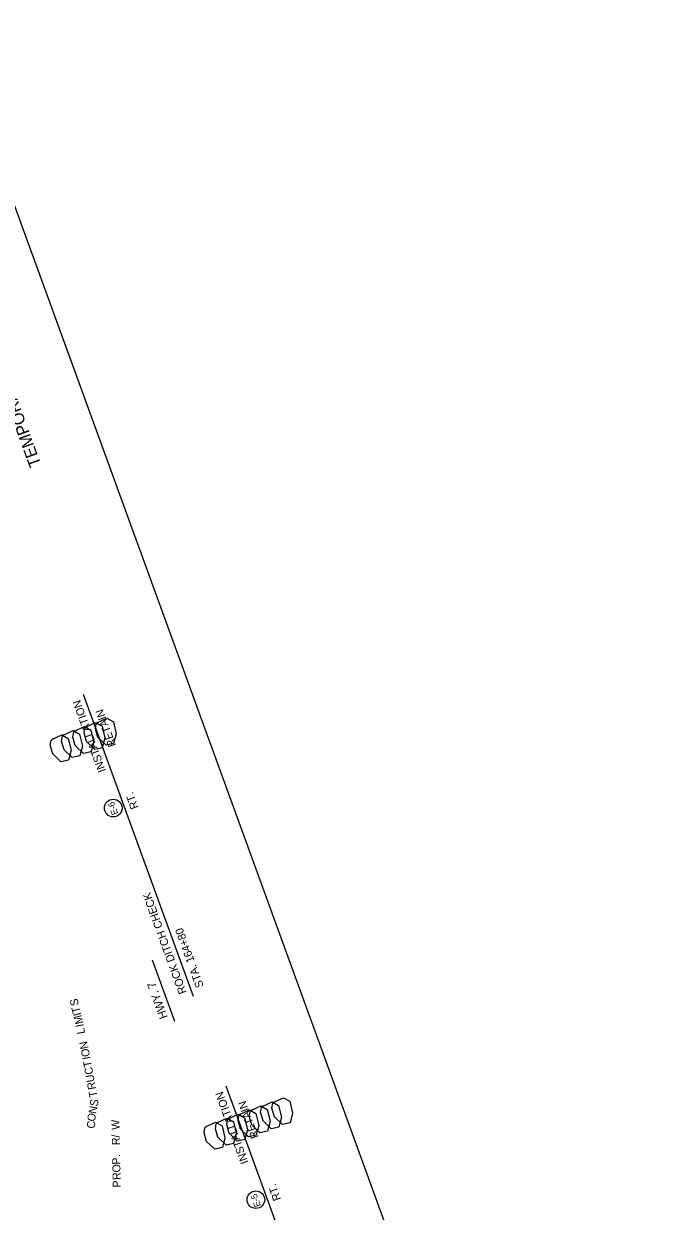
# Model space of a CAD drawing. Extents: x 986289 to 987754, y 1871116 to 1872971.
# Drawn here: x 987265 to 987754, y 1872081 to 1872971 of the extents above; entities that cross this region are included whole.
import ezdxf

# ---------------------------------------------------------------- set-up
doc = ezdxf.new("R2010")
doc.units = 0
for name, color, linetype in [('1', 7, 'Continuous'), ('44', 7, 'Continuous'), ('60', 7, 'Continuous'), ('NO PLOT', 7, 'Continuous'), ('R_Draft', 7, 'Continuous'), ('S_TREE', 7, 'Continuous')]:
    doc.layers.add(name, color=color, linetype=linetype)

msp = doc.modelspace()

# ---------------------------------------------------------------- linework, layer by layer
at = {"layer": '1'}
for centre in [(987331.7, 1872383.22), (987438.58, 1872089.57)]:
    msp.add_circle(centre, 6.61, dxfattribs=at)
at = {"layer": '44'}
for p, q in [((987391.94, 1872241.79), (987309.51, 1872468.26)), ((987377.86, 1872223.17), (987361.16, 1872269.07)), ((987498.82, 1871948.14), (987416.39, 1872174.61))]:
    msp.add_line(p, q, dxfattribs=at)
at = {"layer": 'NO PLOT'}
msp.add_lwpolyline([(987753.66, 1871472.09), (987208.01, 1872971.24), (986718.28, 1872792.99), (986821.23, 1872510.15), (986884.66, 1872533.24), (987030.02, 1872133.87), (986966.59, 1872110.78), (987064.47, 1871841.86), (987122.5, 1871862.99), (987239.7, 1871540.99), (987181.66, 1871519.87), (987263.93, 1871293.85)], close=True, dxfattribs=at)
msp.add_lwpolyline([(987753.66, 1871472.09), (987208.01, 1872971.24), (986718.28, 1872792.99), (986821.23, 1872510.15), (986884.66, 1872533.24), (987030.02, 1872133.87), (986966.59, 1872110.78), (987064.47, 1871841.86), (987122.5, 1871862.99), (987239.7, 1871540.99), (987181.66, 1871519.87), (987263.93, 1871293.85)], close=True, dxfattribs=at)
msp.add_lwpolyline([(987753.66, 1871472.09), (987208.01, 1872971.24), (986718.28, 1872792.99), (986821.23, 1872510.15), (986884.66, 1872533.24), (987030.02, 1872133.87), (986966.59, 1872110.78), (987064.47, 1871841.86), (987122.5, 1871862.99), (987239.7, 1871540.99), (987181.66, 1871519.87), (987263.93, 1871293.85)], close=True, dxfattribs=at)
msp.add_lwpolyline([(987753.66, 1871472.09), (987208.01, 1872971.24), (986718.28, 1872792.99), (986821.23, 1872510.15), (986884.66, 1872533.24), (987030.02, 1872133.87), (986966.59, 1872110.78), (987064.47, 1871841.86), (987122.5, 1871862.99), (987239.7, 1871540.99), (987181.66, 1871519.87), (987263.93, 1871293.85)], close=True, dxfattribs=at)
at = {"layer": 'S_TREE'}
for points in [[(987311.01, 1872443.91), (987318.48, 1872447.4), (987323.31, 1872444.67), (987325.46, 1872435.84), (987323.52, 1872428.46), (987317.82, 1872427.18), (987311.74, 1872433.07), (987309.88, 1872439.51), (987310.5, 1872443.17), (987311.69, 1872444.39)], [(987311.01, 1872443.91), (987318.48, 1872447.4), (987323.31, 1872444.67), (987325.46, 1872435.84), (987323.52, 1872428.46), (987317.82, 1872427.18), (987311.74, 1872433.07), (987309.88, 1872439.51), (987310.5, 1872443.17), (987311.69, 1872444.39)], [(987311.01, 1872443.91), (987318.48, 1872447.4), (987323.31, 1872444.67), (987325.46, 1872435.84), (987323.52, 1872428.46), (987317.82, 1872427.18), (987311.74, 1872433.07), (987309.88, 1872439.51), (987310.5, 1872443.17), (987311.69, 1872444.39)], [(987311.01, 1872443.91), (987318.48, 1872447.4), (987323.31, 1872444.67), (987325.46, 1872435.84), (987323.52, 1872428.46), (987317.82, 1872427.18), (987311.74, 1872433.07), (987309.88, 1872439.51), (987310.5, 1872443.17), (987311.69, 1872444.39)], [(987319.46, 1872446.99), (987326.94, 1872450.48), (987331.77, 1872447.74), (987333.92, 1872438.92), (987331.98, 1872431.53), (987326.28, 1872430.26), (987320.2, 1872436.15), (987318.34, 1872442.59), (987318.95, 1872446.25), (987320.15, 1872447.47)], [(987319.46, 1872446.99), (987326.94, 1872450.48), (987331.77, 1872447.74), (987333.92, 1872438.92), (987331.98, 1872431.53), (987326.28, 1872430.26), (987320.2, 1872436.15), (987318.34, 1872442.59), (987318.95, 1872446.25), (987320.15, 1872447.47)], [(987285.64, 1872434.68), (987293.11, 1872438.16), (987297.94, 1872435.43), (987300.09, 1872426.6), (987298.15, 1872419.22), (987292.45, 1872417.95), (987286.37, 1872423.83), (987284.51, 1872430.28), (987285.12, 1872433.93), (987286.32, 1872435.15)], [(987294.09, 1872437.76), (987301.57, 1872441.24), (987306.4, 1872438.51), (987308.54, 1872429.68), (987306.61, 1872422.3), (987300.91, 1872421.03), (987294.83, 1872426.91), (987292.97, 1872433.36), (987293.58, 1872437.01), (987294.78, 1872438.23)], [(987294.09, 1872437.76), (987301.57, 1872441.24), (987306.4, 1872438.51), (987308.54, 1872429.68), (987306.61, 1872422.3), (987300.91, 1872421.03), (987294.83, 1872426.91), (987292.97, 1872433.36), (987293.58, 1872437.01), (987294.78, 1872438.23)], [(987302.55, 1872440.84), (987310.02, 1872444.32), (987314.85, 1872441.59), (987317, 1872432.76), (987315.07, 1872425.38), (987309.36, 1872424.11), (987303.28, 1872429.99), (987301.43, 1872436.44), (987302.04, 1872440.09), (987303.23, 1872441.31)], [(987302.55, 1872440.84), (987310.02, 1872444.32), (987314.85, 1872441.59), (987317, 1872432.76), (987315.07, 1872425.38), (987309.36, 1872424.11), (987303.28, 1872429.99), (987301.43, 1872436.44), (987302.04, 1872440.09), (987303.23, 1872441.31)], [(987443.26, 1872159.49), (987450.73, 1872162.98), (987455.56, 1872160.25), (987457.71, 1872151.42), (987455.78, 1872144.04), (987450.07, 1872142.76), (987443.99, 1872148.65), (987442.14, 1872155.09), (987442.75, 1872158.75), (987443.94, 1872159.97)], [(987451.72, 1872162.57), (987459.19, 1872166.06), (987464.02, 1872163.32), (987466.17, 1872154.5), (987464.23, 1872147.11), (987458.53, 1872145.84), (987452.45, 1872151.73), (987450.59, 1872158.17), (987451.21, 1872161.83), (987452.4, 1872163.05)], [(987417.89, 1872150.26), (987425.36, 1872153.75), (987430.19, 1872151.01), (987432.34, 1872142.18), (987430.41, 1872134.8), (987424.7, 1872133.53), (987418.62, 1872139.41), (987416.77, 1872145.86), (987417.38, 1872149.51), (987418.57, 1872150.74)], [(987417.89, 1872150.26), (987425.36, 1872153.75), (987430.19, 1872151.01), (987432.34, 1872142.18), (987430.41, 1872134.8), (987424.7, 1872133.53), (987418.62, 1872139.41), (987416.77, 1872145.86), (987417.38, 1872149.51), (987418.57, 1872150.74)], [(987426.35, 1872153.34), (987433.82, 1872156.82), (987438.65, 1872154.09), (987440.8, 1872145.26), (987438.86, 1872137.88), (987433.16, 1872136.61), (987427.08, 1872142.49), (987425.22, 1872148.94), (987425.83, 1872152.59), (987427.03, 1872153.81)], [(987434.8, 1872156.42), (987442.28, 1872159.9), (987447.11, 1872157.17), (987449.25, 1872148.34), (987447.32, 1872140.96), (987441.62, 1872139.69), (987435.54, 1872145.57), (987433.68, 1872152.02), (987434.29, 1872155.67), (987435.49, 1872156.89)], [(987400.97, 1872144.1), (987408.45, 1872147.59), (987413.28, 1872144.86), (987415.43, 1872136.03), (987413.49, 1872128.65), (987407.79, 1872127.37), (987401.71, 1872133.26), (987399.85, 1872139.7), (987400.46, 1872143.36), (987401.66, 1872144.58)], [(987400.97, 1872144.1), (987408.45, 1872147.59), (987413.28, 1872144.86), (987415.43, 1872136.03), (987413.49, 1872128.65), (987407.79, 1872127.37), (987401.71, 1872133.26), (987399.85, 1872139.7), (987400.46, 1872143.36), (987401.66, 1872144.58)], [(987409.43, 1872147.18), (987416.9, 1872150.67), (987421.73, 1872147.93), (987423.88, 1872139.11), (987421.95, 1872131.72), (987416.24, 1872130.45), (987410.16, 1872136.34), (987408.31, 1872142.78), (987408.92, 1872146.44), (987410.11, 1872147.66)], [(987409.43, 1872147.18), (987416.9, 1872150.67), (987421.73, 1872147.93), (987423.88, 1872139.11), (987421.95, 1872131.72), (987416.24, 1872130.45), (987410.16, 1872136.34), (987408.31, 1872142.78), (987408.92, 1872146.44), (987410.11, 1872147.66)]]:
    msp.add_lwpolyline(points, dxfattribs=at)

# ---------------------------------------------------------------- texts
at = {"layer": '1'}
for s, p in [('E-6 ', (987335.44, 1872379.05)), ('E-5 ', (987442.43, 1872085.11))]:
    msp.add_text(s, height=4.8, rotation=110, dxfattribs=at).set_placement(p)
at = {"layer": '44'}
for s, height, p in [('INSTALLATION', 6, (987326.28, 1872411.2)), ('RETAIN', 6, (987333.91, 1872430.27)), ('RT.', 6, (987350.71, 1872383.61)), ('ROCK DITCH CHECK', 6, (987386.77, 1872245.01)), ('STA. 164+80', 6, (987399.61, 1872249.69)), ('HWY. 7', 6.25, (987372.65, 1872226.43)), ('INSTALLATION', 6, (987433.16, 1872117.55)), ('RETAIN', 6, (987440.79, 1872136.61)), ('RT.', 6, (987457.6, 1872089.96))]:
    msp.add_text(s, height=height, rotation=110, dxfattribs=at).set_placement(p)
at = {"layer": '60'}
msp.add_text('TEMPORARY EROSION CONTROL DETAILS', height=9, rotation=110, dxfattribs=at).set_placement((987277.82, 1872640.76))
at = {"layer": 'R_Draft'}
for s, rotation, p in [('S', 101.43623, (987305.97, 1872235.52)), ('T', 104.87321, (987307.28, 1872230.18)), ('I', 104.87321, (987307.79, 1872228.26)), ('M', 104.87321, (987309.44, 1872222.05)), ('I', 100.09804, (987309.71, 1872219.57)), ('L', 100.09804, (987310.65, 1872214.27)), ('N', 103.08822, (987313.21, 1872203.2)), ('O', 101.12912, (987314.34, 1872197.25)), ('I', 101.12912, (987314.73, 1872195.3)), ('T', 100.22799, (987315.8, 1872189.45)), ('C', 100.22799, (987316.81, 1872183.87)), ('U', 100.29018, (987317.84, 1872178.2)), ('R', 100.29018, (987318.85, 1872172.62)), ('T', 100.35239, (987319.9, 1872166.87)), ('S', 80.05059, (987319.92, 1872159.17)), ('O', 80.05059, (987317.93, 1872147.82)), ('N', 80.05059, (987318.94, 1872153.59)), ('C', 85.69841, (987317.86, 1872142.72)), ('W', 91.20729, (987336.47, 1872142.02)), ('/', 91.20729, (987336.6, 1872136.16)), ('R', 91.20729, (987336.72, 1872130.5)), ('P', 91.20729, (987337.03, 1872115.9)), ('.', 91.20729, (987336.91, 1872121.57)), ('O', 91.20729, (987337.15, 1872110.04)), ('R', 91.20729, (987337.27, 1872104.38)), ('P', 91.20729, (987337.39, 1872098.71))]:
    msp.add_text(s, height=6, rotation=rotation, dxfattribs=at).set_placement(p)

doc.saveas('drawing.dxf')
